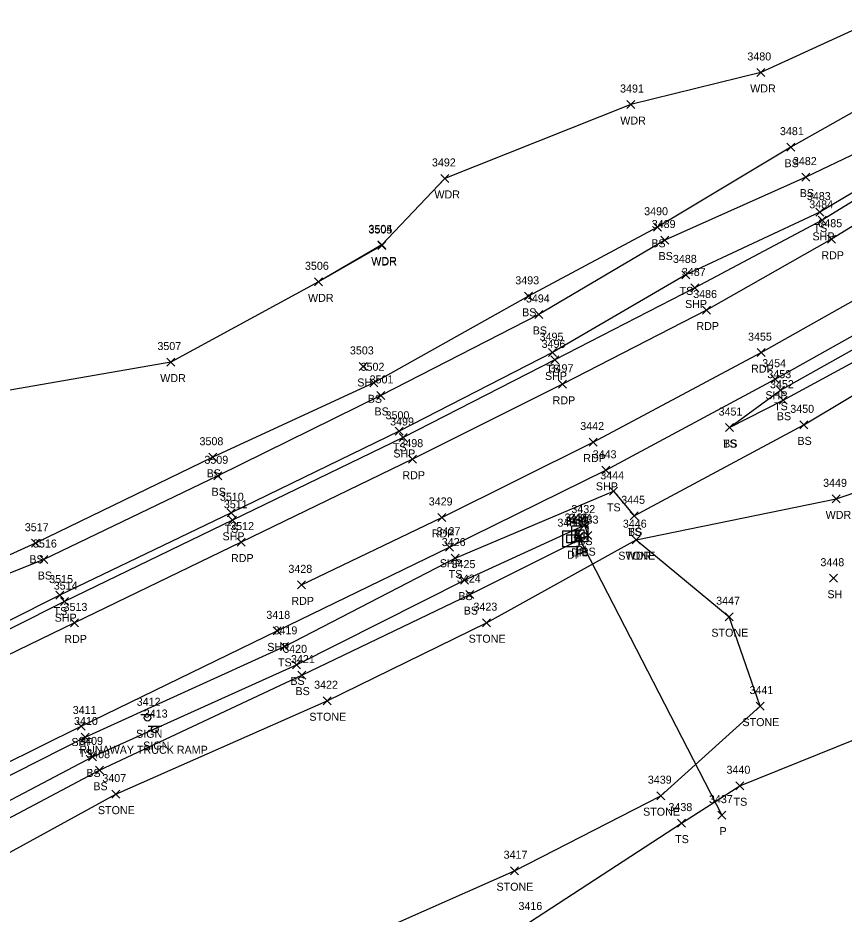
# Model space of a CAD drawing. Extents: x 1623612 to 1625808, y 621345 to 627748.
# Drawn here: x 1625229.6 to 1625436, y 626896.7 to 627120.5 of the extents above; entities that cross this region are included whole.
import ezdxf

# ---------------------------------------------------------------- set-up
doc = ezdxf.new("R2010")
doc.units = 0
for name, color, linetype in [('D_A', 7, 'Continuous'), ('D_I', 7, 'Continuous'), ('D_TIC', 7, 'Continuous'), ('DCP', 7, 'Continuous'), ('DS', 7, 'Continuous'), ('L_A', 7, 'Continuous'), ('L_I', 7, 'Continuous'), ('L_TIC', 7, 'Continuous'), ('LASF', 7, 'Continuous'), ('LAWA', 7, 'Continuous'), ('LELB', 7, 'Continuous'), ('LSOGP', 7, 'Continuous'), ('P_A', 7, 'Continuous'), ('P_I', 7, 'Continuous'), ('P_TIC', 7, 'Continuous'), ('PET', 7, 'Continuous'), ('PSP', 7, 'Continuous'), ('S_A', 7, 'Continuous'), ('S_C', 7, 'Continuous'), ('S_I', 7, 'Continuous'), ('SSGN', 7, 'Continuous')]:
    doc.layers.add(name, color=color, linetype=linetype)

msp = doc.modelspace()

# ---------------------------------------------------------------- linework, layer by layer
at = {"layer": 'D_TIC'}
for points in [[(1625368.46, 626990.74), (1625370.46, 626992.74)], [(1625370.46, 626990.74), (1625368.46, 626992.74)], [(1625368.67, 626990.01), (1625370.67, 626992.01)], [(1625370.67, 626990.01), (1625368.67, 626992.01)], [(1625368.74, 626989.77), (1625370.74, 626991.77)], [(1625370.74, 626989.77), (1625368.74, 626991.77)], [(1625404.47, 626920.41), (1625406.47, 626922.41)], [(1625406.47, 626920.41), (1625404.47, 626922.41)]]:
    msp.add_lwpolyline(points, dxfattribs=at)
at = {"layer": 'DCP'}
msp.add_lwpolyline([(1625369.74, 626990.77), (1625405.47, 626921.41)], dxfattribs=at)
at = {"layer": 'DS'}
for p, q in [((1625367.94, 626993.67), (1625371.94, 626993.67)), ((1625367.94, 626989.67), (1625367.94, 626993.67)), ((1625371.94, 626993.67), (1625371.94, 626989.67)), ((1625365.7, 626992.45), (1625369.7, 626992.45)), ((1625365.7, 626988.45), (1625365.7, 626992.45)), ((1625366.7, 626989.45), (1625366.7, 626991.45)), ((1625366.7, 626991.45), (1625368.7, 626991.45)), ((1625368.7, 626991.45), (1625368.7, 626989.45)), ((1625368.94, 626990.67), (1625368.94, 626992.67)), ((1625368.94, 626992.67), (1625370.94, 626992.67)), ((1625369.7, 626992.45), (1625369.7, 626988.45)), ((1625369.94, 626991.67), (1625369.94, 626991.67)), ((1625369.94, 626991.67), (1625369.94, 626991.67)), ((1625370.94, 626992.67), (1625370.94, 626990.67)), ((1625368.7, 626989.45), (1625366.7, 626989.45)), ((1625367.71, 626990.45), (1625367.71, 626990.45)), ((1625367.71, 626990.45), (1625367.71, 626990.45)), ((1625371.94, 626989.67), (1625367.94, 626989.67)), ((1625370.94, 626990.67), (1625368.94, 626990.67)), ((1625369.7, 626988.45), (1625365.7, 626988.45))]:
    msp.add_line(p, q, dxfattribs=at)
at = {"layer": 'L_TIC'}
for points in [[(1625414.15, 627105.89), (1625416.15, 627107.89)], [(1625416.15, 627105.89), (1625414.15, 627107.89)], [(1625381.7, 627097.88), (1625383.7, 627099.88)], [(1625383.7, 627097.88), (1625381.7, 627099.88)], [(1625421.64, 627087.23), (1625423.64, 627089.23)], [(1625423.64, 627087.23), (1625421.64, 627089.23)], [(1625335.27, 627079.42), (1625337.27, 627081.42)], [(1625337.27, 627079.42), (1625335.27, 627081.42)], [(1625425.45, 627079.76), (1625427.45, 627081.76)], [(1625427.45, 627079.76), (1625425.45, 627081.76)], [(1625428.94, 627071.01), (1625430.94, 627073.01)], [(1625430.94, 627071.01), (1625428.94, 627073.01)], [(1625388.38, 627067.23), (1625390.38, 627069.23)], [(1625390.38, 627067.23), (1625388.38, 627069.23)], [(1625390.19, 627064.04), (1625392.19, 627066.04)], [(1625392.19, 627064.04), (1625390.19, 627066.04)], [(1625319.48, 627062.82), (1625321.48, 627064.82)], [(1625321.48, 627062.82), (1625319.48, 627064.82)], [(1625319.52, 627062.67), (1625321.52, 627064.67)], [(1625321.52, 627062.67), (1625319.52, 627064.67)], [(1625395.47, 627055.33), (1625397.47, 627057.33)], [(1625397.47, 627055.33), (1625395.47, 627057.33)], [(1625303.7, 627053.6), (1625305.7, 627055.6)], [(1625305.7, 627053.6), (1625303.7, 627055.6)], [(1625356.1, 627049.98), (1625358.1, 627051.98)], [(1625358.1, 627049.98), (1625356.1, 627051.98)], [(1625358.75, 627045.45), (1625360.75, 627047.45)], [(1625360.75, 627045.45), (1625358.75, 627047.45)], [(1625362.17, 627035.91), (1625364.17, 627037.91)], [(1625364.17, 627035.91), (1625362.17, 627037.91)], [(1625266.78, 627033.56), (1625268.78, 627035.56)], [(1625268.78, 627033.56), (1625266.78, 627035.56)], [(1625314.87, 627032.47), (1625316.87, 627034.47)], [(1625316.87, 627032.47), (1625314.87, 627034.47)], [(1625317.54, 627028.39), (1625319.54, 627030.39)], [(1625319.54, 627028.39), (1625317.54, 627030.39)], [(1625319.22, 627025.23), (1625321.22, 627027.23)], [(1625321.22, 627025.23), (1625319.22, 627027.23)], [(1625419.07, 627026.54), (1625421.07, 627028.54)], [(1625421.07, 627026.54), (1625419.07, 627028.54)], [(1625419.73, 627024.04), (1625421.73, 627026.04)], [(1625421.73, 627024.04), (1625419.73, 627026.04)], [(1625323.86, 627016.28), (1625325.86, 627018.28)], [(1625325.86, 627016.28), (1625323.86, 627018.28)], [(1625406.31, 627017.21), (1625408.31, 627019.21)], [(1625408.31, 627017.21), (1625406.31, 627019.21)], [(1625406.31, 627017.21), (1625408.31, 627019.21)], [(1625408.31, 627017.21), (1625406.31, 627019.21)], [(1625424.88, 627017.88), (1625426.88, 627019.88)], [(1625426.88, 627017.88), (1625424.88, 627019.88)], [(1625277.3, 627009.79), (1625279.3, 627011.79)], [(1625279.3, 627009.79), (1625277.3, 627011.79)], [(1625278.53, 627005.16), (1625280.53, 627007.16)], [(1625280.53, 627005.16), (1625278.53, 627007.16)], [(1625377.33, 627001.28), (1625379.33, 627003.28)], [(1625379.33, 627001.28), (1625377.33, 627003.28)], [(1625433, 626999.4), (1625435, 627001.4)], [(1625435, 626999.4), (1625433, 627001.4)], [(1625281.83, 626995.93), (1625283.83, 626997.93)], [(1625283.83, 626995.93), (1625281.83, 626997.93)], [(1625382.56, 626995.16), (1625384.56, 626997.16)], [(1625384.56, 626995.16), (1625382.56, 626997.16)], [(1625382.56, 626995.16), (1625384.56, 626997.16)], [(1625384.56, 626995.16), (1625382.56, 626997.16)], [(1625370.11, 626992.85), (1625372.11, 626994.85)], [(1625372.11, 626992.85), (1625370.11, 626994.85)], [(1625370.92, 626990.22), (1625372.92, 626992.22)], [(1625372.92, 626990.22), (1625370.92, 626992.22)], [(1625370.92, 626990.22), (1625372.92, 626992.22)], [(1625372.92, 626990.22), (1625370.92, 626992.22)], [(1625383.02, 626989.2), (1625385.02, 626991.2)], [(1625385.02, 626989.2), (1625383.02, 626991.2)], [(1625383.02, 626989.2), (1625385.02, 626991.2)], [(1625385.02, 626989.2), (1625383.02, 626991.2)], [(1625233, 626988.32), (1625235, 626990.32)], [(1625235, 626988.32), (1625233, 626990.32)], [(1625235.1, 626984.25), (1625237.1, 626986.25)], [(1625237.1, 626984.25), (1625235.1, 626986.25)], [(1625337.79, 626984.61), (1625339.79, 626986.61)], [(1625339.79, 626984.61), (1625337.79, 626986.61)], [(1625340.19, 626979.11), (1625342.19, 626981.11)], [(1625342.19, 626979.11), (1625340.19, 626981.11)], [(1625432.32, 626979.58), (1625434.32, 626981.58)], [(1625434.32, 626979.58), (1625432.32, 626981.58)], [(1625239.1, 626975.36), (1625241.1, 626977.36)], [(1625241.1, 626975.36), (1625239.1, 626977.36)], [(1625341.51, 626975.49), (1625343.51, 626977.49)], [(1625343.51, 626975.49), (1625341.51, 626977.49)], [(1625406.28, 626969.97), (1625408.28, 626971.97)], [(1625408.28, 626969.97), (1625406.28, 626971.97)], [(1625406.28, 626969.97), (1625408.28, 626971.97)], [(1625408.28, 626969.97), (1625406.28, 626971.97)], [(1625345.65, 626968.47), (1625347.65, 626970.47)], [(1625347.65, 626968.47), (1625345.65, 626970.47)], [(1625295.15, 626962.56), (1625297.15, 626964.56)], [(1625297.15, 626962.56), (1625295.15, 626964.56)], [(1625298.22, 626957.94), (1625300.22, 626959.94)], [(1625300.22, 626957.94), (1625298.22, 626959.94)], [(1625299.49, 626955.39), (1625301.49, 626957.39)], [(1625301.49, 626955.39), (1625299.49, 626957.39)], [(1625305.85, 626948.98), (1625307.85, 626950.98)], [(1625307.85, 626948.98), (1625305.85, 626950.98)], [(1625414.04, 626947.64), (1625416.04, 626949.64)], [(1625416.04, 626947.64), (1625414.04, 626949.64)], [(1625245.39, 626939.92), (1625247.39, 626941.92)], [(1625247.39, 626939.92), (1625245.39, 626941.92)], [(1625247.24, 626934.95), (1625249.24, 626936.95)], [(1625249.24, 626934.95), (1625247.24, 626936.95)], [(1625249, 626931.63), (1625251, 626933.63)], [(1625251, 626931.63), (1625249, 626933.63)], [(1625408.95, 626927.75), (1625410.95, 626929.75)], [(1625410.95, 626927.75), (1625408.95, 626929.75)], [(1625253.03, 626925.66), (1625255.03, 626927.66)], [(1625255.03, 626925.66), (1625253.03, 626927.66)], [(1625389.22, 626925.27), (1625391.22, 626927.27)], [(1625391.22, 626925.27), (1625389.22, 626927.27)], [(1625394.36, 626918.42), (1625396.36, 626920.42)], [(1625396.36, 626918.42), (1625394.36, 626920.42)], [(1625352.61, 626906.53), (1625354.61, 626908.53)], [(1625354.61, 626906.53), (1625352.61, 626908.53)]]:
    msp.add_lwpolyline(points, dxfattribs=at)
at = {"layer": 'LASF'}
for points in [[(1625177.06, 626894.7), (1625218.88, 626907.4), (1625254.03, 626926.66), (1625306.85, 626949.98), (1625346.65, 626969.47), (1625384.02, 626990.2), (1625407.28, 626970.97)], [(1625160.13, 626885.56), (1625166.23, 626871.01), (1625184.49, 626848.17), (1625202.58, 626840.63), (1625237.88, 626854), (1625291.03, 626879.76), (1625353.61, 626907.53), (1625390.22, 626926.27), (1625415.04, 626948.64), (1625407.28, 626970.97)]]:
    msp.add_lwpolyline(points, dxfattribs=at)
at = {"layer": 'LAWA'}
for points in [[(1625415.15, 627106.89), (1625382.7, 627098.88), (1625336.27, 627080.42), (1625320.48, 627063.82), (1625320.52, 627063.67), (1625304.7, 627054.6), (1625267.78, 627034.56), (1625224.16, 627026.96), (1625202.12, 627004.43), (1625150.28, 626974.64), (1625120.61, 626985.6), (1625102.29, 627003.55), (1625124.36, 627037.24), (1625145.75, 627068.46), (1625178.32, 627095.73), (1625213.7, 627126.41), (1625246.32, 627163.64), (1625275.84, 627203.6), (1625300.5, 627239.13), (1625315, 627239.75)], [(1625384.02, 626990.2), (1625434, 627000.4), (1625482.59, 627016.81), (1625515.44, 627028.63)]]:
    msp.add_lwpolyline(points, dxfattribs=at)
at = {"layer": 'LELB'}
for points in [[(1625469.29, 627095.38), (1625429.94, 627072.01), (1625396.47, 627056.33), (1625363.17, 627036.91), (1625324.86, 627017.28), (1625282.83, 626996.93), (1625240.1, 626976.36), (1625200.92, 626956.72), (1625164.36, 626938.31), (1625128.12, 626918.34), (1625094.57, 626896.89), (1625066.91, 626876.48), (1625035.19, 626854.3), (1625018.18, 626859.5), (1625006.28, 626868.94), (1625007.56, 626879.04), (1625022.39, 626921.76), (1625036.67, 626956.96), (1625050.15, 626986.83), (1625070.28, 627027.73), (1625085.48, 627058.74), (1625111, 627101.13), (1625130.83, 627129.7)], [(1625459.45, 627108.93), (1625422.64, 627088.23), (1625389.38, 627068.23), (1625357.1, 627050.98), (1625318.54, 627029.39), (1625278.3, 627010.79), (1625234, 626989.32), (1625195.14, 626971.7)], [(1625466.12, 627099.72), (1625426.45, 627080.76), (1625391.19, 627065.04), (1625359.75, 627046.45), (1625320.22, 627026.23), (1625279.53, 627006.16), (1625236.1, 626985.25), (1625196.36, 626969.39), (1625155.89, 626955.67), (1625118.73, 626941.79)], [(1625407.31, 627018.21), (1625420.07, 627027.54), (1625454.37, 627046.77), (1625487.14, 627068.05)], [(1625407.31, 627018.21), (1625420.73, 627025.04), (1625456.07, 627044.18), (1625488.88, 627065.43)], [(1625383.56, 626996.16), (1625425.88, 627018.88), (1625459.69, 627039.1), (1625493.08, 627059.7)], [(1625206.27, 626920.6), (1625246.39, 626940.92), (1625296.15, 626963.56), (1625338.79, 626985.61), (1625378.33, 627002.28), (1625383.56, 626996.16)], [(1625209.28, 626915.51), (1625248.24, 626935.95), (1625299.22, 626958.94), (1625341.19, 626980.11), (1625371.11, 626993.85), (1625371.92, 626991.22)], [(1625083.53, 626780.74), (1625137.04, 626804.12), (1625178.43, 626816.77), (1625245.42, 626840.4), (1625308.04, 626871.64), (1625357.38, 626894.72), (1625395.36, 626919.42), (1625409.95, 626928.75), (1625453.5, 626946.29), (1625490.76, 626971.58), (1625536.74, 626991.35)], [(1625176.09, 626897.9), (1625212.13, 626912.6), (1625250, 626932.63), (1625300.49, 626956.39), (1625342.51, 626976.49), (1625371.92, 626991.22)]]:
    msp.add_lwpolyline(points, dxfattribs=at)
at = {"layer": 'LSOGP'}
for points in [[(1625449.92, 627122.76), (1625415.15, 627106.89), (1625382.7, 627098.88), (1625336.27, 627080.42), (1625320.48, 627063.82), (1625304.7, 627054.6), (1625267.78, 627034.56), (1625224.16, 627026.96)], [(1625357.38, 626894.72), (1625395.36, 626919.42), (1625409.95, 626928.75), (1625453.5, 626946.29)]]:
    msp.add_lwpolyline(points, dxfattribs=at)
at = {"layer": 'P_TIC'}
for points in [[(1625429.53, 627068.96), (1625431.53, 627070.96)], [(1625431.53, 627068.96), (1625429.53, 627070.96)], [(1625431.8, 627064.24), (1625433.8, 627066.24)], [(1625433.8, 627064.24), (1625431.8, 627066.24)], [(1625397.71, 627052.07), (1625399.71, 627054.07)], [(1625399.71, 627052.07), (1625397.71, 627054.07)], [(1625400.59, 627046.56), (1625402.59, 627048.56)], [(1625402.59, 627046.56), (1625400.59, 627048.56)], [(1625362.72, 627034.1), (1625364.72, 627036.1)], [(1625364.72, 627034.1), (1625362.72, 627036.1)], [(1625414.24, 627035.91), (1625416.24, 627037.91)], [(1625416.24, 627035.91), (1625414.24, 627037.91)], [(1625364.67, 627028.01), (1625366.67, 627030.01)], [(1625366.67, 627028.01), (1625364.67, 627030.01)], [(1625417.78, 627029.28), (1625419.78, 627031.28)], [(1625419.78, 627029.28), (1625417.78, 627031.28)], [(1625324.83, 627014.73), (1625326.83, 627016.73)], [(1625326.83, 627014.73), (1625324.83, 627016.73)], [(1625372.33, 627013.59), (1625374.33, 627015.59)], [(1625374.33, 627013.59), (1625372.33, 627015.59)], [(1625327.14, 627009.31), (1625329.14, 627011.31)], [(1625329.14, 627009.31), (1625327.14, 627011.31)], [(1625375.43, 627006.53), (1625377.43, 627008.53)], [(1625377.43, 627006.53), (1625375.43, 627008.53)], [(1625282.17, 626994.05), (1625284.17, 626996.05)], [(1625284.17, 626994.05), (1625282.17, 626996.05)], [(1625334.49, 626994.75), (1625336.49, 626996.75)], [(1625336.49, 626994.75), (1625334.49, 626996.75)], [(1625284.33, 626988.61), (1625286.33, 626990.61)], [(1625286.33, 626988.61), (1625284.33, 626990.61)], [(1625336.44, 626987.32), (1625338.44, 626989.32)], [(1625338.44, 626987.32), (1625336.44, 626989.32)], [(1625299.42, 626977.92), (1625301.42, 626979.92)], [(1625301.42, 626977.92), (1625299.42, 626979.92)], [(1625240.24, 626973.73), (1625242.24, 626975.73)], [(1625242.24, 626973.73), (1625240.24, 626975.73)], [(1625242.69, 626968.41), (1625244.69, 626970.41)], [(1625244.69, 626968.41), (1625242.69, 626970.41)], [(1625293.34, 626966.43), (1625295.34, 626968.43)], [(1625295.34, 626966.43), (1625293.34, 626968.43)], [(1625244.42, 626942.67), (1625246.42, 626944.67)], [(1625246.42, 626942.67), (1625244.42, 626944.67)]]:
    msp.add_lwpolyline(points, dxfattribs=at)
at = {"layer": 'PET'}
for points in [[(1625473.25, 627090.09), (1625432.8, 627065.24), (1625401.59, 627047.56), (1625365.67, 627029.01), (1625328.14, 627010.31), (1625285.33, 626989.61), (1625243.69, 626969.41), (1625203.66, 626950.01), (1625167.56, 626931.17), (1625131.52, 626910.23), (1625100.02, 626889.97), (1625071.13, 626869.72), (1625042.82, 626845.85)], [(1625300.42, 626978.92), (1625335.49, 626995.75), (1625373.33, 627014.59), (1625415.24, 627036.91), (1625448.84, 627055.85), (1625481.73, 627076.41)]]:
    msp.add_lwpolyline(points, dxfattribs=at)
at = {"layer": 'PSP'}
for points in [[(1625470.03, 627094.27), (1625430.53, 627069.96), (1625398.71, 627053.07), (1625363.72, 627035.1), (1625325.83, 627015.73), (1625283.17, 626995.05), (1625241.24, 626974.73), (1625201.61, 626954.83)], [(1625205.02, 626923.68), (1625245.42, 626943.67), (1625294.34, 626967.43), (1625337.44, 626988.32), (1625376.43, 627007.53), (1625418.78, 627030.28), (1625452.84, 627049.39), (1625486.07, 627069.84)]]:
    msp.add_lwpolyline(points, dxfattribs=at)
at = {"layer": 'SSGN'}
for p, q in [((1625260.33, 626946.58), (1625263.66, 626946.58)), ((1625261.98, 626945.75), (1625261.98, 626945.75)), ((1625262.11, 626943.64), (1625265.44, 626943.64)), ((1625263.76, 626942.81), (1625263.76, 626942.81))]:
    msp.add_line(p, q, dxfattribs=at)
for centre in [(1625261.98, 626945.75), (1625263.76, 626942.81)]:
    msp.add_circle(centre, 0.833, dxfattribs=at)

# ---------------------------------------------------------------- texts
at = {"layer": 'D_A'}
for s, p in [('DI', (1625366.76, 626985.45)), ('DIB', (1625367.77, 626986.01)), ('P', (1625368.84, 626986.74)), ('DI', (1625369, 626986.67)), ('P', (1625369.12, 626985.77)), ('P', (1625404.85, 626916.41))]:
    msp.add_text(s, height=2, dxfattribs=at).set_placement(p)
at = {"layer": 'D_I'}
for s, p in [('3436', (1625366.15, 626994.74)), ('3434', (1625366.41, 626994.01)), ('3435', (1625366.48, 626993.77)), ('3431', (1625367.25, 626994.67)), ('3430', (1625364.36, 626993.45)), ('3437', (1625402.21, 626924.41))]:
    msp.add_text(s, height=2, dxfattribs=at).set_placement(p)
at = {"layer": 'L_A'}
for s, p in [('WDR', (1625412.51, 627101.89)), ('WDR', (1625380.06, 627093.88)), ('BS', (1625421.08, 627083.23)), ('WDR', (1625333.64, 627075.42)), ('BS', (1625424.89, 627075.76)), ('TS', (1625428.35, 627067.01)), ('BS', (1625387.82, 627063.23)), ('WDR', (1625317.85, 627058.82)), ('WDR', (1625317.88, 627058.67)), ('BS', (1625389.63, 627060.04)), ('WDR', (1625302.06, 627049.6)), ('TS', (1625394.88, 627051.33)), ('BS', (1625355.54, 627045.98)), ('BS', (1625358.19, 627041.45)), ('TS', (1625361.58, 627031.91)), ('WDR', (1625265.14, 627029.56)), ('SH', (1625314.36, 627028.47)), ('BS', (1625316.98, 627024.39)), ('BS', (1625318.66, 627021.23)), ('TS', (1625418.48, 627022.54)), ('BS', (1625419.17, 627020.04)), ('BS', (1625424.32, 627013.88)), ('TS', (1625323.27, 627012.28)), ('TS', (1625405.72, 627013.21)), ('BS', (1625405.75, 627013.21)), ('BS', (1625276.74, 627005.79)), ('BS', (1625277.97, 627001.16)), ('TS', (1625376.74, 626997.28)), ('WDR', (1625431.36, 626995.4)), ('TS', (1625281.24, 626991.93)), ('TS', (1625381.97, 626991.16)), ('BS', (1625382, 626991.16)), ('BS', (1625369.56, 626988.85)), ('BS', (1625370.36, 626986.22)), ('BS', (1625370.36, 626986.22)), ('STONE', (1625379.57, 626985.2)), ('WDR', (1625381.39, 626985.2)), ('BS', (1625232.44, 626984.32)), ('BS', (1625234.55, 626980.25)), ('TS', (1625337.2, 626980.61)), ('BS', (1625339.63, 626975.11)), ('SH', (1625431.8, 626975.58)), ('TS', (1625238.51, 626971.36)), ('BS', (1625340.95, 626971.49)), ('STONE', (1625402.82, 626965.97)), ('STONE', (1625402.82, 626965.97)), ('STONE', (1625342.19, 626964.47)), ('TS', (1625294.56, 626958.56)), ('BS', (1625297.66, 626953.94)), ('BS', (1625298.93, 626951.39)), ('STONE', (1625302.39, 626944.98)), ('STONE', (1625410.59, 626943.64)), ('TS', (1625244.8, 626935.92)), ('BS', (1625246.68, 626930.95)), ('BS', (1625248.44, 626927.63)), ('TS', (1625408.36, 626923.75)), ('STONE', (1625249.58, 626921.66)), ('STONE', (1625385.76, 626921.27)), ('TS', (1625393.77, 626914.42)), ('STONE', (1625349.15, 626902.53))]:
    msp.add_text(s, height=2, dxfattribs=at).set_placement(p)
at = {"layer": 'L_I'}
for s, p in [('3480', (1625411.81, 627109.89)), ('3491', (1625380.01, 627101.88)), ('3481', (1625419.95, 627091.23)), ('3492', (1625333.02, 627083.42)), ('3482', (1625423.19, 627083.76)), ('3483', (1625426.68, 627075.01)), ('3490', (1625386.03, 627071.23)), ('3489', (1625387.92, 627068.04)), ('3504', (1625317.15, 627066.82)), ('3505', (1625317.18, 627066.67)), ('3488', (1625393.21, 627059.33)), ('3506', (1625301.3, 627057.6)), ('3493', (1625353.84, 627053.98)), ('3494', (1625356.49, 627049.45)), ('3495', (1625359.91, 627039.91)), ('3507', (1625264.44, 627037.56)), ('3503', (1625312.53, 627036.47)), ('3502', (1625315.2, 627032.39)), ('3453', (1625416.81, 627030.54)), ('3501', (1625317.45, 627029.23)), ('3452', (1625417.47, 627028.04)), ('3451', (1625404.62, 627021.21)), ('3451', (1625404.62, 627021.21)), ('3450', (1625422.53, 627021.88)), ('3500', (1625321.43, 627020.28)), ('3508', (1625274.96, 627013.79)), ('3509', (1625276.18, 627009.16)), ('3444', (1625375.07, 627005.28)), ('3449', (1625430.73, 627003.4)), ('3510', (1625280.05, 626999.93)), ('3445', (1625380.3, 626999.16)), ('3445', (1625380.3, 626999.16)), ('3432', (1625367.85, 626996.85)), ('3433', (1625368.66, 626994.22)), ('3433', (1625368.66, 626994.22)), ('3517', (1625231.31, 626992.32)), ('3446', (1625380.71, 626993.2)), ('3446', (1625380.71, 626993.2)), ('3516', (1625233.36, 626988.25)), ('3426', (1625335.48, 626988.61)), ('3425', (1625337.93, 626983.11)), ('3448', (1625430.06, 626983.58)), ('3515', (1625237.41, 626979.36)), ('3424', (1625339.25, 626979.49)), ('3447', (1625404.02, 626973.97)), ('3447', (1625404.02, 626973.97)), ('3423', (1625343.39, 626972.47)), ('3419', (1625293.45, 626966.56)), ('3420', (1625295.87, 626961.94)), ('3421', (1625297.8, 626959.39)), ('3422', (1625303.59, 626952.98)), ('3441', (1625412.35, 626951.64)), ('3410', (1625243.61, 626943.92)), ('3409', (1625244.89, 626938.95)), ('3408', (1625246.66, 626935.63)), ('3440', (1625406.6, 626931.75)), ('3407', (1625250.69, 626929.66)), ('3439', (1625386.95, 626929.27)), ('3438', (1625392.1, 626922.42)), ('3417', (1625350.92, 626910.53)), ('3416', (1625354.63, 626897.72))]:
    msp.add_text(s, height=2, dxfattribs=at).set_placement(p)
at = {"layer": 'P_A'}
for s, p in [('SHP', (1625428.07, 627064.96)), ('RDP', (1625430.29, 627060.24)), ('SHP', (1625396.25, 627048.07)), ('RDP', (1625399.07, 627042.56)), ('RDP', (1625412.73, 627031.91)), ('SHP', (1625361.26, 627030.1)), ('SHP', (1625416.32, 627025.28)), ('RDP', (1625363.16, 627024.01)), ('SHP', (1625323.37, 627010.73)), ('RDP', (1625370.82, 627009.59)), ('RDP', (1625325.63, 627005.31)), ('SHP', (1625373.96, 627002.53)), ('SHP', (1625280.7, 626990.05)), ('RDP', (1625332.98, 626990.75)), ('RDP', (1625282.82, 626984.61)), ('SHP', (1625334.97, 626983.32)), ('RDP', (1625297.9, 626973.92)), ('SHP', (1625238.78, 626969.73)), ('RDP', (1625241.18, 626964.41)), ('SHP', (1625291.88, 626962.43)), ('SHP', (1625242.96, 626938.67))]:
    msp.add_text(s, height=2, dxfattribs=at).set_placement(p)
at = {"layer": 'P_I'}
for s, p in [('3484', (1625427.27, 627072.96)), ('3485', (1625429.54, 627068.24)), ('3487', (1625395.45, 627056.07)), ('3486', (1625398.27, 627050.56)), ('3455', (1625411.98, 627039.91)), ('3496', (1625360.41, 627038.1)), ('3497', (1625362.41, 627032.01)), ('3454', (1625415.52, 627033.28)), ('3499', (1625322.57, 627018.73)), ('3442', (1625370.07, 627017.59)), ('3498', (1625324.88, 627013.31)), ('3443', (1625373.17, 627010.53)), ('3429', (1625332.22, 626998.75)), ('3511', (1625281.04, 626998.05)), ('3512', (1625282.63, 626992.61)), ('3427', (1625334.18, 626991.32)), ('3428', (1625297.16, 626981.92)), ('3514', (1625238.55, 626977.73)), ('3513', (1625241, 626972.41)), ('3418', (1625291.65, 626970.43)), ('3411', (1625243.29, 626946.67))]:
    msp.add_text(s, height=2, dxfattribs=at).set_placement(p)
at = {"layer": 'S_A'}
for p in [(1625259.12, 626940.73), (1625260.89, 626937.79)]:
    msp.add_text('SIGN', height=2, dxfattribs=at).set_placement(p)
at = {"layer": 'S_C'}
msp.add_text('RUNAWAY TRUCK RAMP', height=2, dxfattribs=at).set_placement((1625244.93, 626936.73))
at = {"layer": 'S_I'}
for s, p in [('3412', (1625259.27, 626948.73)), ('3413', (1625261.04, 626945.79))]:
    msp.add_text(s, height=2, dxfattribs=at).set_placement(p)

doc.saveas('drawing.dxf')
